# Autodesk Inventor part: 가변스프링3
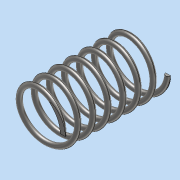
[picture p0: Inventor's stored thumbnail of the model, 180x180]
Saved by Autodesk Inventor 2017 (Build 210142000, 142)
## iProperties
Part Number: 가변스프링3
Material: 스테인레스 스틸
Document SubType Name: Modeling
Designer: MRC
Density: 8 g/cm^3
Appearance: 반연마
Mass: 10.9393 g
Surface Area: 27.6351 cm^2
Volume: 1.36741 cm^3
Author: MRC
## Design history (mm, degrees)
sketch "스케치1"
  geometry: L1 (0, 0)-(10, 0); L2 (10, 0)-(10, 41.411); L3 (10, 41.411)-(0, 41.411); L4 (0, 41.411)-(0, 0); C1 r 1 at (10, 0)
  constraints: 8 end point, 2 parallel, 1 centre point, 1 coincident, 1 horizontal, 1 perpendicular
  dimensions: "d0" = 41.4112 distance of L3.end L1.start (derived); "d1" = 20 diameter of L2 L4; "d2" = 2 diameter of C1
feature "코일1" sketch "스케치1" pitch "d3" = 10; turns "d5" = 7; dims "d4" = 41.4112 (= d0), "d6" = 0, angle "d7" = 90 deg, angle "d8" = 90 deg, "d9" = 0, "d10" = 0
sketch "스케치2"
  geometry: L1 (-20, 41.411)-(20, 41.411); L2 (20, 41.411)-(20, 0); L3 (20, 0)-(-20, 0); L4 (-20, 0)-(-20, 41.411); L5 (0, 41.411)-(0, 0) reference; 2 further points
  constraints: 8 end point, 2 midpoint, 2 parallel, 1 coincident, 1 horizontal, 1 perpendicular
  dimensions: "d11" = 40 distance of L1.start L1.end
extrude "돌출1" sketch "스케치2" stored distance "d12" = 0; taper "d13" = 0 deg
node "솔리드1"
